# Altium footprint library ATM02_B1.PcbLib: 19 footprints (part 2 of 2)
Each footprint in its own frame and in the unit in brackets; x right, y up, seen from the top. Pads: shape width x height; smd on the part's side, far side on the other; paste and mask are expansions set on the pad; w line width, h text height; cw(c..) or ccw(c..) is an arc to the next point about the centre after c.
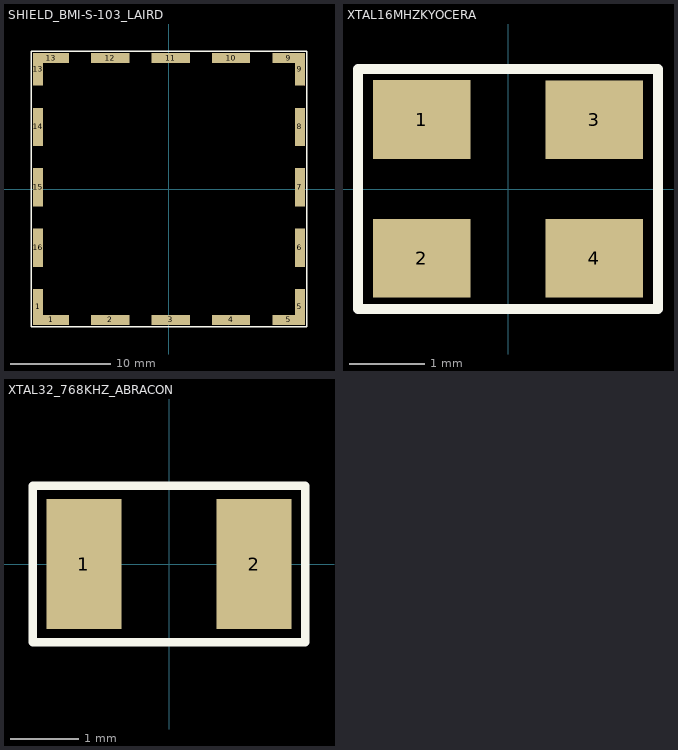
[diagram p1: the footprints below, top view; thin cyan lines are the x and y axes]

## SHIELD_BMI-S-103_LAIRD [mm]
pads (20):
  rect 1x3.57 smd: 1(-13.005,-11.72) 5(13.005,-11.72)
  rect 3.57x1 smd: 1(-11.72,-13.005) 13(-11.72,13.005)
  rect 3.8x1 smd: 2(-5.835,-13.005) 3(0.165,-13.005) 4(6.165,-13.005) 10(6.165,13.005) 11(0.165,13.005) 12(-5.835,13.005)
  rect 3.24x1 smd: 5(11.885,-13.005) 9(11.885,13.005)
  rect 1x3.8 smd: 6(13.005,-5.835) 7(13.005,0.165) 8(13.005,6.165) 14(-13.005,6.165) 15(-13.005,0.165) 16(-13.005,-5.835)
  rect 1x3.24 smd: 9(13.005,11.885) 13(-13.005,11.885)
Top Layer:
  lines w0.001: 13.505,10.305 13.505,12.505
Top Overlay:
  lines w0.127: -13.7,-13.7 13.7,-13.7 13.7,13.7 -13.7,13.7 -13.7,-13.7

## XTAL16MHZKYOCERA [mm]
height 0.9
pads (4):
  rect 1.3x1.05 smd: 1(-1.15,0.925) 2(-1.15,-0.925) 3(1.15,0.925) 4(1.15,-0.925)
Top Overlay:
  lines w0.127: -2,-1.6 2,-1.6 2,1.6 -2,1.6 -2,-1.6

## XTAL32_768KHZ_ABRACON [mm]
height 0.9
pads (2):
  rect 1.1x1.9 smd: 1(-1.25,0) 2(1.25,0)
Top Overlay:
  lines w0.127: -2,-1.15 2,-1.15 2,1.15 -2,1.15 -2,-1.15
